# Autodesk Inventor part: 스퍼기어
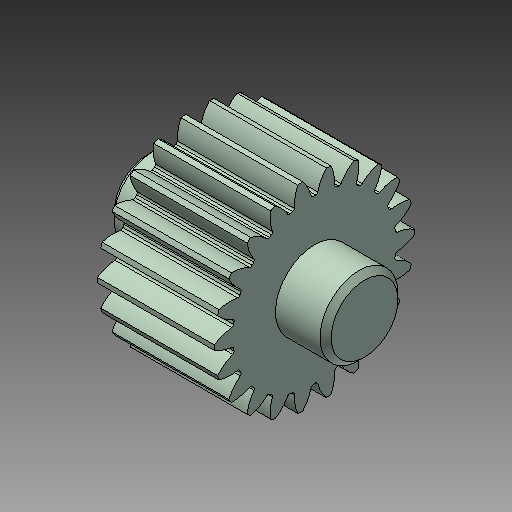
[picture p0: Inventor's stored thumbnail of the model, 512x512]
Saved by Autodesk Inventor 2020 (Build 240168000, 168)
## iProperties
Created: 2024-02
Part Number: 스퍼기어
Material: 강철, 탄소
Document SubType Name: Modeling
Designer: mdu-01
Density: 1 g/cm^3
Appearance: 기본값(1)
Author: mdu-01
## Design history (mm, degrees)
sketch "스케치1"
  geometry: L1 (-19.5, 0)-(19.5, 0); L2 (19.5, 0)-(19.5, 6); L3 (18.5, 7)-(10.5, 7); L4 (10.5, 7)-(10.5, 14.625); L5 (10.5, 14.625)-(-10.5, 14.625); L6 (-10.5, 14.625)-(-10.5, 7); L7 (-10.5, 7)-(-18.5, 7); L8 (-19.5, 6)-(-19.5, 0); L9 (-18.5, 7)-(-19.5, 6); L10 (19.5, 6)-(18.5, 7); L11 (-10.5, 16.5)-(10.5, 16.5); 4 further points
  constraints: 22 end point, 6 parallel, 6 point on line, 2 collinear, 2 perpendicular, 1 coincident, 1 horizontal, 1 midpoint
  dimensions: "d0" = 1 distance of L7.end point (-19.5, 7); "d1" = 1 distance of L8.start point (-19.5, 7) (= d0); "d2" = 1 distance of L2.end point (19.5, 7) (= d0); "d3" = 1 distance of L3.start point (19.5, 7) (= d2); "d4" = 9 distance between parallel lines of L8 L6; "d5" = 21 distance between parallel lines of L4 L6; "d6" = 33 diameter of L11 L1; "d7" = 1.875 distance between parallel lines of L5 L11; "d8" = 14 diameter of L7 L1
revolve "회전1" sketch "스케치1" stored, may be unused: angle "d9" = 90 deg
sketch "스케치2" dims "d10" = 33
  geometry: L1 (0, 0)-(18, 0); A1 r 18 centre (0, 0) between (17.995, -0.428) and (17.995, 0.428); A2 r 7.045 centre (14.16, 5.482) between (14.542, -1.553) and (17.995, -0.428); A3 r 7.045 centre (14.16, -5.482) between (17.995, 0.428) and (14.542, 1.553); A4 r 14.625 centre (0, 0) between (14.542, -1.553) and (14.542, 1.553); 4 further points
  constraints: 10 point on circle, 4 centre point, 3 symmetric about line, 2 coincident, 2 end point, 1 horizontal, 8 other
  dimensions: "d11" = 1.5 dimension on A1; "d12" = 1.1775 distance from line of point (16.458, -1.178) L1; "d13" = 0.75 vertical distance of A1.start point (16.458, -1.178); "d14" = 0.375 vertical distance of A2.start point (16.458, -1.178)
extrude "돌출1" join sketch "스케치2" stored distance "d15" = 10; taper "d16" = 0 deg
fillet "모깎기1" dims "d17" = 0.375
node "솔리드1"
pattern_circular "원형 패턴1" dims angle "d19" = 360 deg
